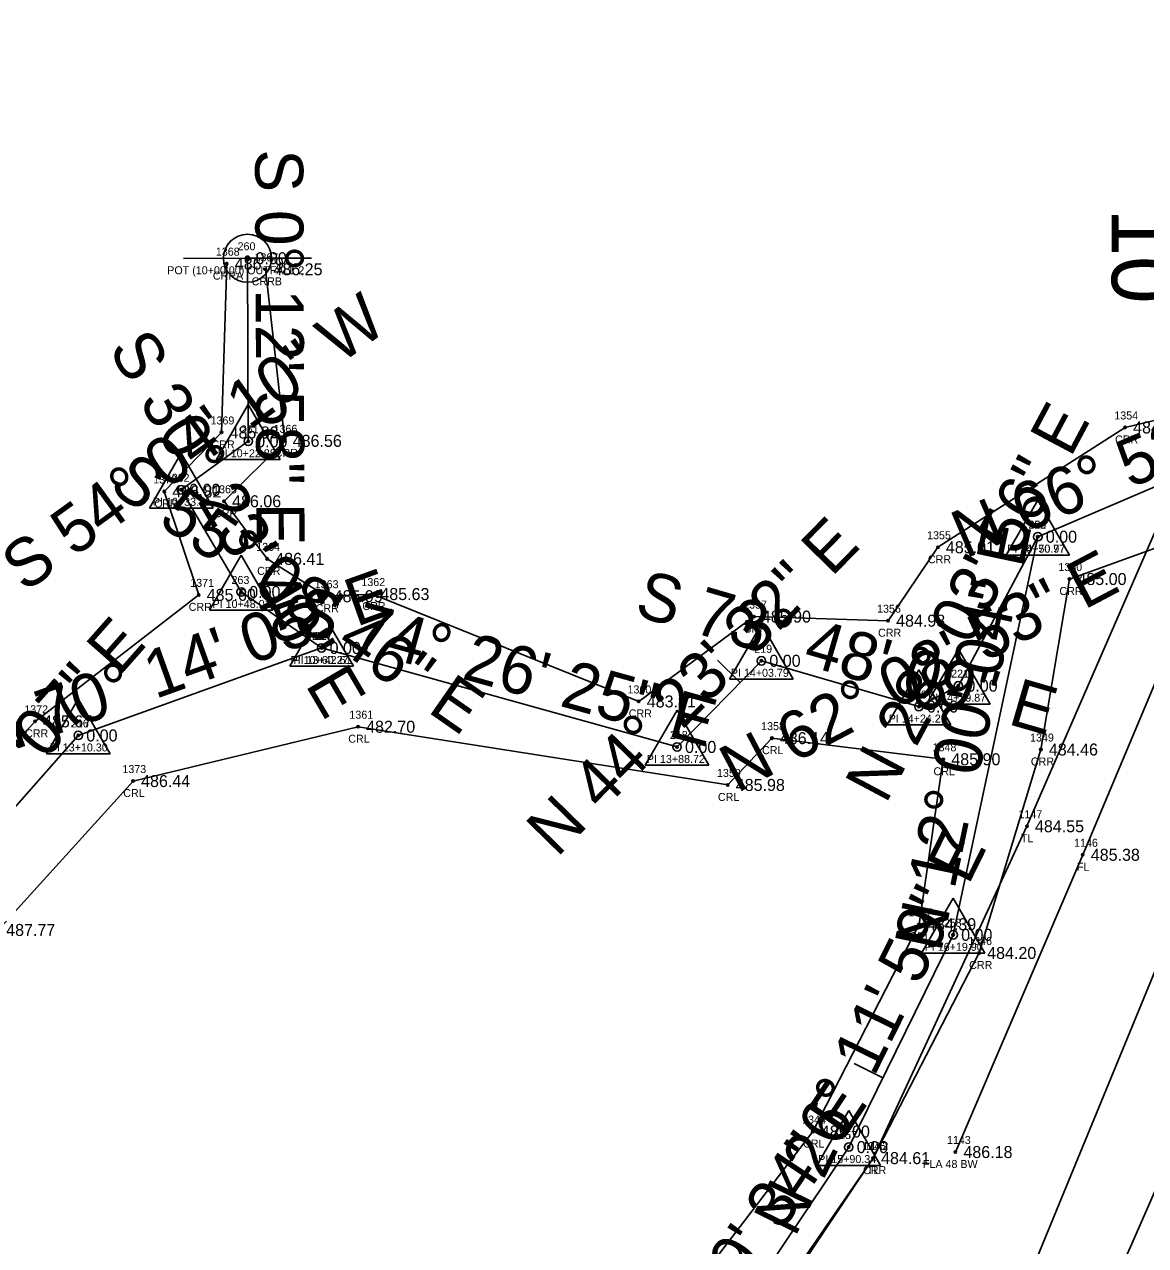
# Model space of a CAD drawing. Extents: x 1649047 to 1650429, y 896228 to 898747.
# Drawn here: x 1649708.6 to 1649848.7, y 897330 to 897482.7 of the extents above; entities that cross this region are included whole.
import ezdxf

# ---------------------------------------------------------------- set-up
doc = ezdxf.new("R2010")
doc.units = 0
for name, color, linetype in [('RD_EX_Fence_Other', 7, 'Continuous'), ('RD_EX_Fence_Other_txCode', 7, 'Continuous'), ('RD_EX_H2O', 7, 'Continuous'), ('RD_EX_H2O_txCode', 7, 'Continuous'), ('RD_EX_Road', 7, 'Continuous'), ('RD_EX_TX_Fence_Other_ELEV', 7, 'Continuous'), ('RD_EX_TX_H2O_ELEV', 7, 'Continuous'), ('RD_EX_TX_VEG_ELEV', 7, 'Continuous'), ('RD_EX_VEG', 7, 'Continuous'), ('RD_EX_VEG_txCode', 7, 'Continuous'), ('RD_HC_Cl', 7, 'Continuous'), ('RD_HC_Data', 7, 'Continuous'), ('RD_HC_Data_Tic', 7, 'Continuous'), ('RD_HC_Survey_ELEV', 7, 'Continuous'), ('RD_HC_TX_Sta50', 7, 'Continuous'), ('RD_HC_txCode', 7, 'Continuous'), ('RD_SMD_Locator', 7, 'Continuous')]:
    doc.layers.add(name, color=color, linetype=linetype)

msp = doc.modelspace()

# ---------------------------------------------------------------- linework, layer by layer
at = {"layer": 'RD_EX_Fence_Other'}
msp.add_lwpolyline([(1649824.95, 897341.74), (1649840.87, 897378.89), (1649858.83, 897421.59)], dxfattribs=at)
at = {"layer": 'RD_EX_H2O'}
for points in [[(1649733.89, 897452.78), (1649733.23, 897431.68), (1649726.08, 897424.3), (1649730.38, 897411.38), (1649709.93, 897395.57), (1649696.43, 897381.39), (1649633.87, 897388.98), (1649608.54, 897369.49), (1649592.36, 897367.34), (1649564.26, 897376.33), (1649519.76, 897372.2), (1649499.24, 897352.4), (1649435.41, 897352.44)], [(1649868.8, 897437.77), (1649846.16, 897432.3), (1649822.76, 897417.33), (1649816.54, 897408.15), (1649799.76, 897408.66), (1649785.38, 897398.06), (1649752.08, 897411.48), (1649746.25, 897411.21), (1649738.94, 897415.88), (1649733.55, 897423.08), (1649741.13, 897430.63), (1649738.72, 897452.07)], [(1649610.78, 897003.58), (1649606.65, 897007.8), (1649603.49, 897018.01), (1649613.66, 897065.71), (1649613.8, 897087.62), (1649648.77, 897123.4), (1649673.15, 897145.36), (1649677.84, 897170.04), (1649704.36, 897195), (1649732.98, 897211.32), (1649741.05, 897244.13), (1649760.18, 897240.39), (1649790.48, 897304.8), (1649814.66, 897340.98), (1649827.92, 897366.62), (1649835.63, 897392.05), (1649839.2, 897413.36), (1649851.88, 897417.91), (1649868.27, 897424.7)], [(1649723.06, 897216.5), (1649737.55, 897250.43), (1649753.58, 897247.01), (1649784.63, 897314.89), (1649807.13, 897344.3), (1649820.41, 897370.21), (1649823.44, 897390.83), (1649802.01, 897393.47), (1649796.5, 897387.62), (1649750.3, 897394.9), (1649722.18, 897388.11), (1649705.32, 897369.5), (1649633.55, 897374.58), (1649615.45, 897358.48), (1649595.58, 897353.05), (1649593.32, 897314.38), (1649587.49, 897281.56)]]:
    msp.add_lwpolyline(points, dxfattribs=at)
at = {"layer": 'RD_EX_Road'}
msp.add_lwpolyline([(1649459.38, 896805.71), (1649486.55, 896839.62), (1649513.65, 896873.34), (1649538.22, 896902.56), (1649549.43, 896916.62), (1649583.1, 896957.27), (1649614.8, 896995.02), (1649647.06, 897035.69), (1649677.62, 897074.51), (1649708.33, 897114.44), (1649735.5, 897151.61), (1649762.11, 897192.19), (1649788.21, 897235.29), (1649812.17, 897279.73), (1649834.32, 897326.54), (1649852.94, 897371.82), (1649867.51, 897411.96)], dxfattribs=at)
at = {"layer": 'RD_EX_VEG'}
msp.add_lwpolyline([(1649617.18, 897070.52), (1649712.19, 897191.88), (1649745.96, 897241.38), (1649814.66, 897340.98), (1649833.89, 897382.46), (1649865.2, 897454.4), (1649884.45, 897522.02), (1649904.5, 897665.19), (1649923.9, 897762.32), (1649882.75, 898072.18)], dxfattribs=at)
at = {"layer": 'RD_HC_Cl'}
for p, q in [((1649736.48, 897453.45), (1649736.57, 897430.57)), ((1649835.25, 897418.65), (1649869.38, 897433.21)), ((1649736.57, 897430.57), (1649728.2, 897424.51)), ((1649728.2, 897424.51), (1649735.69, 897411.74)), ((1649824.67, 897368.89), (1649835.25, 897418.65)), ((1649825.32, 897400.03), (1649835.25, 897418.65)), ((1649735.69, 897411.74), (1649745.74, 897404.74)), ((1649715.33, 897393.81), (1649745.74, 897404.74)), ((1649745.74, 897404.74), (1649790.16, 897392.37)), ((1649790.16, 897392.37), (1649800.7, 897403.14)), ((1649800.7, 897403.14), (1649820.39, 897397.42)), ((1649820.39, 897397.42), (1649825.32, 897400.03)), ((1649699.1, 897375.44), (1649715.33, 897393.81)), ((1649811.62, 897342.36), (1649824.67, 897368.89)), ((1649788.75, 897308.24), (1649811.62, 897342.36))]:
    msp.add_line(p, q, dxfattribs=at)
msp.add_arc((1648799.37, 897792.37), 1145, 320.82481, 10.99954, dxfattribs=at)
at = {"layer": 'RD_HC_Data'}
for p, q in [((1649732.59, 897428.28), (1649736.57, 897435.16)), ((1649736.57, 897435.16), (1649740.54, 897428.28)), ((1649724.23, 897422.22), (1649728.2, 897429.1)), ((1649728.2, 897429.1), (1649732.17, 897422.22)), ((1649732.59, 897428.28), (1649740.54, 897428.28)), ((1649724.23, 897422.22), (1649732.17, 897422.22)), ((1649831.28, 897416.35), (1649835.25, 897423.23)), ((1649831.28, 897416.35), (1649835.25, 897423.23)), ((1649835.25, 897423.23), (1649839.22, 897416.35)), ((1649835.25, 897423.23), (1649839.22, 897416.35)), ((1649731.72, 897409.45), (1649735.69, 897416.33)), ((1649735.69, 897416.33), (1649739.66, 897409.45)), ((1649831.28, 897416.35), (1649839.22, 897416.35)), ((1649831.28, 897416.35), (1649839.22, 897416.35)), ((1649731.72, 897409.45), (1649739.66, 897409.45)), ((1649741.77, 897402.45), (1649745.74, 897409.33)), ((1649741.77, 897402.45), (1649745.74, 897409.33)), ((1649745.74, 897409.33), (1649749.71, 897402.45)), ((1649745.74, 897409.33), (1649749.71, 897402.45)), ((1649796.73, 897400.85), (1649800.7, 897407.73)), ((1649800.7, 897407.73), (1649804.67, 897400.85)), ((1649821.35, 897397.73), (1649825.32, 897404.61)), ((1649825.32, 897404.61), (1649829.29, 897397.73)), ((1649741.77, 897402.45), (1649749.71, 897402.45)), ((1649741.77, 897402.45), (1649749.71, 897402.45)), ((1649796.73, 897400.85), (1649804.67, 897400.85)), ((1649816.42, 897395.13), (1649820.39, 897402.01)), ((1649820.39, 897402.01), (1649824.36, 897395.13)), ((1649711.36, 897391.52), (1649715.33, 897398.4)), ((1649715.33, 897398.4), (1649719.3, 897391.52)), ((1649786.19, 897390.08), (1649790.17, 897396.96)), ((1649790.17, 897396.96), (1649794.13, 897390.08)), ((1649821.35, 897397.73), (1649829.29, 897397.73)), ((1649816.42, 897395.13), (1649824.36, 897395.13)), ((1649711.36, 897391.52), (1649719.3, 897391.52)), ((1649786.19, 897390.08), (1649794.13, 897390.08)), ((1649820.7, 897366.6), (1649824.67, 897373.48)), ((1649824.67, 897373.48), (1649828.64, 897366.6)), ((1649820.7, 897366.6), (1649828.64, 897366.6)), ((1649807.65, 897340.07), (1649811.62, 897346.95)), ((1649811.62, 897346.95), (1649815.59, 897340.07)), ((1649807.65, 897340.07), (1649815.59, 897340.07))]:
    msp.add_line(p, q, dxfattribs=at)
for centre, radius in [((1649736.48, 897453.45), 3), ((1649736.48, 897453.45), 0.282), ((1649736.57, 897430.57), 0.529), ((1649728.2, 897424.51), 0.529), ((1649835.25, 897418.65), 0.529), ((1649835.25, 897418.65), 0.529), ((1649735.69, 897411.74), 0.529), ((1649745.74, 897404.74), 0.529), ((1649745.74, 897404.74), 0.529), ((1649800.7, 897403.14), 0.529), ((1649825.32, 897400.03), 0.529), ((1649820.39, 897397.42), 0.529), ((1649715.33, 897393.81), 0.529), ((1649790.16, 897392.37), 0.529), ((1649824.67, 897368.89), 0.529), ((1649811.62, 897342.36), 0.529)]:
    msp.add_circle(centre, radius, dxfattribs=at)
at = {"layer": 'RD_HC_Data_Tic'}
for p, q in [((1649736.48, 897453.45), (1649728.48, 897453.42)), ((1649736.48, 897453.45), (1649744.48, 897453.48)), ((1649798.05, 897400.43), (1649795.2, 897403.23)), ((1649815.89, 897351.03), (1649812.3, 897352.8))]:
    msp.add_line(p, q, dxfattribs=at)
at = {"layer": 'RD_SMD_Locator'}
for centre in [(1649733.89, 897452.78), (1649736.48, 897453.45), (1649738.72, 897452.07), (1649733.23, 897431.68), (1649846.16, 897432.3), (1649736.57, 897430.57), (1649741.13, 897430.63), (1649726.08, 897424.3), (1649728.2, 897424.51), (1649733.55, 897423.08), (1649835.25, 897418.65), (1649835.25, 897418.65), (1649822.76, 897417.33), (1649738.94, 897415.88), (1649839.2, 897413.36), (1649730.38, 897411.38), (1649735.69, 897411.74), (1649752.08, 897411.48), (1649746.25, 897411.21), (1649799.76, 897408.66), (1649816.54, 897408.15), (1649745.74, 897404.74), (1649745.74, 897404.74), (1649800.7, 897403.14), (1649825.32, 897400.03), (1649785.38, 897398.06), (1649820.39, 897397.42), (1649709.93, 897395.57), (1649750.3, 897394.9), (1649715.33, 897393.81), (1649802.01, 897393.47), (1649790.16, 897392.37), (1649835.63, 897392.05), (1649823.44, 897390.83), (1649722.18, 897388.11), (1649796.5, 897387.62), (1649833.89, 897382.46), (1649840.87, 897378.89), (1649820.41, 897370.21), (1649824.67, 897368.89), (1649827.92, 897366.62), (1649807.13, 897344.3), (1649811.62, 897342.36), (1649824.95, 897341.74), (1649814.66, 897340.98), (1649814.66, 897340.98)]:
    msp.add_circle(centre, 0.15, dxfattribs=at)

# ---------------------------------------------------------------- texts
at = {"layer": 'RD_EX_Fence_Other_txCode'}
for s, p in [('1146', (1649839.78, 897379.89)), ('FL', (1649840.14, 897376.89)), ('1143', (1649823.89, 897342.74)), ('FLA 48 BW', (1649820.89, 897339.74))]:
    msp.add_text(s, height=1, dxfattribs=at).set_placement(p)
at = {"layer": 'RD_EX_H2O_txCode'}
for s, p in [('1368', (1649732.52, 897453.78)), ('1367', (1649737.35, 897453.07)), ('CRRA', (1649732.15, 897450.78)), ('CRRB', (1649737, 897450.07)), ('1369', (1649731.86, 897432.68)), ('1354', (1649844.81, 897433.3)), ('1366', (1649739.74, 897431.63)), ('CRR', (1649731.98, 897429.68)), ('CRR', (1649844.91, 897430.3)), ('CRR', (1649739.88, 897428.63)), ('1370', (1649724.69, 897425.3)), ('1365', (1649732.18, 897424.08)), ('CRR', (1649724.83, 897422.3)), ('CRR', (1649732.3, 897421.08)), ('1355', (1649821.41, 897418.33)), ('1364', (1649737.57, 897416.88)), ('CRR', (1649821.51, 897415.33)), ('CRR', (1649737.69, 897413.88)), ('1350', (1649837.82, 897414.36)), ('1371', (1649729.32, 897412.38)), ('1363', (1649744.88, 897412.21)), ('1362', (1649750.71, 897412.48)), ('CRR', (1649837.95, 897411.36)), ('CRR', (1649729.13, 897409.38)), ('CRR', (1649745, 897409.21)), ('CRR', (1649750.83, 897409.48)), ('1357', (1649798.42, 897409.66)), ('1356', (1649815.16, 897409.15)), ('CRR', (1649798.51, 897406.66)), ('CRR', (1649815.28, 897406.15)), ('1360', (1649783.97, 897399.06)), ('1372', (1649708.58, 897396.57)), ('1361', (1649749.21, 897395.9)), ('CRR', (1649784.13, 897396.06)), ('1358', (1649800.67, 897394.47)), ('CRR', (1649708.68, 897393.57)), ('CRL', (1649749.07, 897392.9)), ('1349', (1649834.28, 897393.05)), ('CRL', (1649800.78, 897391.47)), ('1348', (1649822.1, 897391.83)), ('CRR', (1649834.38, 897390.05)), ('1373', (1649720.84, 897389.11)), ('1359', (1649795.15, 897388.62)), ('CRL', (1649822.21, 897388.83)), ('CRL', (1649720.95, 897386.11)), ('CRL', (1649795.27, 897385.62)), ('1347', (1649819.06, 897371.21)), ('CRL', (1649819.18, 897368.21)), ('1346', (1649826.55, 897367.62)), ('CRR', (1649826.67, 897364.62)), ('1344', (1649805.79, 897345.3)), ('CRL', (1649805.91, 897342.3)), ('1345', (1649813.31, 897341.98)), ('CRR', (1649813.41, 897338.98))]:
    msp.add_text(s, height=1, dxfattribs=at).set_placement(p)
at = {"layer": 'RD_EX_TX_Fence_Other_ELEV'}
for s, p in [('485.38', (1649841.87, 897378.14)), ('486.18', (1649825.95, 897340.99))]:
    msp.add_text(s, height=1.5, dxfattribs=at).set_placement(p)
at = {"layer": 'RD_EX_TX_H2O_ELEV'}
for s, p in [('486.79', (1649734.89, 897452.03)), ('486.25', (1649739.72, 897451.32)), ('484.47', (1649847.16, 897431.55)), ('485.82', (1649734.23, 897430.93)), ('486.56', (1649742.13, 897429.88)), ('486.82', (1649727.08, 897423.55)), ('486.06', (1649734.55, 897422.33)), ('485.01', (1649823.76, 897416.58)), ('486.41', (1649739.94, 897415.13)), ('485.00', (1649840.2, 897412.61)), ('485.60', (1649731.38, 897410.63)), ('485.99', (1649747.25, 897410.46)), ('485.63', (1649753.08, 897410.73)), ('485.90', (1649800.76, 897407.91)), ('484.98', (1649817.54, 897407.4)), ('483.91', (1649786.38, 897397.31)), ('485.67', (1649710.93, 897394.82)), ('482.70', (1649751.3, 897394.15)), ('486.14', (1649803.01, 897392.72)), ('484.46', (1649836.63, 897391.3)), ('485.90', (1649824.44, 897390.08)), ('486.44', (1649723.18, 897387.36)), ('485.98', (1649797.5, 897386.87)), ('484.39', (1649821.41, 897369.46)), ('487.77', (1649706.32, 897368.75)), ('484.20', (1649828.92, 897365.87)), ('485.00', (1649808.13, 897343.55)), ('484.61', (1649815.66, 897340.23))]:
    msp.add_text(s, height=1.5, dxfattribs=at).set_placement(p)
at = {"layer": 'RD_EX_TX_VEG_ELEV'}
for s, p in [('484.55', (1649834.89, 897381.71)), ('484.61', (1649815.66, 897340.23))]:
    msp.add_text(s, height=1.5, dxfattribs=at).set_placement(p)
at = {"layer": 'RD_EX_VEG_txCode'}
for s, p in [('1147', (1649832.83, 897383.46)), ('TL', (1649833.12, 897380.46)), ('1142', (1649813.59, 897341.98)), ('TL', (1649813.89, 897338.98))]:
    msp.add_text(s, height=1, dxfattribs=at).set_placement(p)
at = {"layer": 'RD_HC_Data'}
for s, rotation, p in [('S 0%%d 12\' 58" E', 270.2161, (1649737.43, 897467.06)), ('S 54%%d 04\' 10" W', 35.9306, (1649708.65, 897411.58)), ('S 30%%d 23\' 40" E', 300.3945, (1649719.02, 897442.13)), ('N 66%%d 53\' 15" E', 23.1125, (1649826.19, 897415.87)), ('N 28%%d 03\' 56" E', 61.9345, (1649816.24, 897385.12)), ('S 55%%d 08\' 46" E', 325.1462, (1649718.93, 897424.63)), ('N 44%%d 23\' 32" E', 45.6078, (1649775.15, 897378.46)), ('N 12%%d 00\' 04" E', 77.9989, (1649823.16, 897366.61)), ('N 62%%d 08\' 53" E', 27.8518, (1649797.65, 897386.54)), ('N 70%%d 14\' 05" E', 19.7654, (1649703.87, 897390.76)), ('S 73%%d 48\' 09" E', 343.8026, (1649784.66, 897408.84)), ('S 74%%d 26\' 25" E', 344.4404, (1649741.98, 897406.83)), ('N 41%%d 27\' 07" E', 48.548, (1649687.95, 897364.32)), ('N 26%%d 11\' 59" E', 63.8002, (1649804.9, 897330.96)), ('N 33%%d 49\' 34" E', 56.1739, (1649783.78, 897302.61))]:
    msp.add_text(s, height=6, rotation=rotation, dxfattribs=at).set_placement(p)
at = {"layer": 'RD_HC_Survey_ELEV'}
for p in [(1649737.48, 897452.7), (1649737.57, 897429.82), (1649729.2, 897423.76), (1649836.25, 897417.9), (1649836.25, 897417.9), (1649736.69, 897410.99), (1649746.74, 897403.99), (1649746.74, 897403.99), (1649801.7, 897402.39), (1649826.32, 897399.28), (1649821.39, 897396.67), (1649716.33, 897393.06), (1649791.16, 897391.62), (1649825.67, 897368.14), (1649812.62, 897341.61)]:
    msp.add_text('0.00', height=1.5, dxfattribs=at).set_placement(p)
at = {"layer": 'RD_HC_TX_Sta50'}
msp.add_text('10', height=8, rotation=270.2161, dxfattribs=at).set_placement((1649844.46, 897459.66))
at = {"layer": 'RD_HC_txCode'}
for s, p in [('260', (1649735.24, 897454.45)), ('POT (10+00.00) OUTFALL 2', (1649726.45, 897451.45)), ('261', (1649735.64, 897431.57)), ('PI 10+22.88', (1649732.75, 897428.57)), ('262', (1649727, 897425.51)), ('PI 10+33.21', (1649724.66, 897422.51)), ('222', (1649834.07, 897419.65)), ('259', (1649834.07, 897419.65)), ('PI 16+70.77', (1649831.41, 897416.65)), ('PI 14+50.97', (1649831.43, 897416.65)), ('263', (1649734.48, 897412.74)), ('PI 10+48.01', (1649732.11, 897409.74)), ('264', (1649744.54, 897405.74)), ('217', (1649744.85, 897405.74)), ('219', (1649799.81, 897404.14)), ('PI 10+60.27', (1649741.86, 897402.74)), ('PI 13+42.61', (1649742.22, 897402.74)), ('PI 14+03.79', (1649796.88, 897401.14)), ('221', (1649824.42, 897401.03)), ('220', (1649819.17, 897398.42)), ('PI 14+29.87', (1649821.54, 897398.03)), ('PI 14+24.29', (1649816.61, 897395.42)), ('216', (1649714.41, 897394.81)), ('218', (1649789.27, 897393.37)), ('PI 13+10.30', (1649711.76, 897391.81)), ('PI 13+88.72', (1649786.39, 897390.37)), ('258', (1649823.49, 897369.89)), ('PI 16+19.90', (1649821.11, 897366.89)), ('257', (1649810.44, 897343.36)), ('PI 15+90.34', (1649807.8, 897340.36))]:
    msp.add_text(s, height=1, dxfattribs=at).set_placement(p)

doc.saveas('drawing.dxf')
